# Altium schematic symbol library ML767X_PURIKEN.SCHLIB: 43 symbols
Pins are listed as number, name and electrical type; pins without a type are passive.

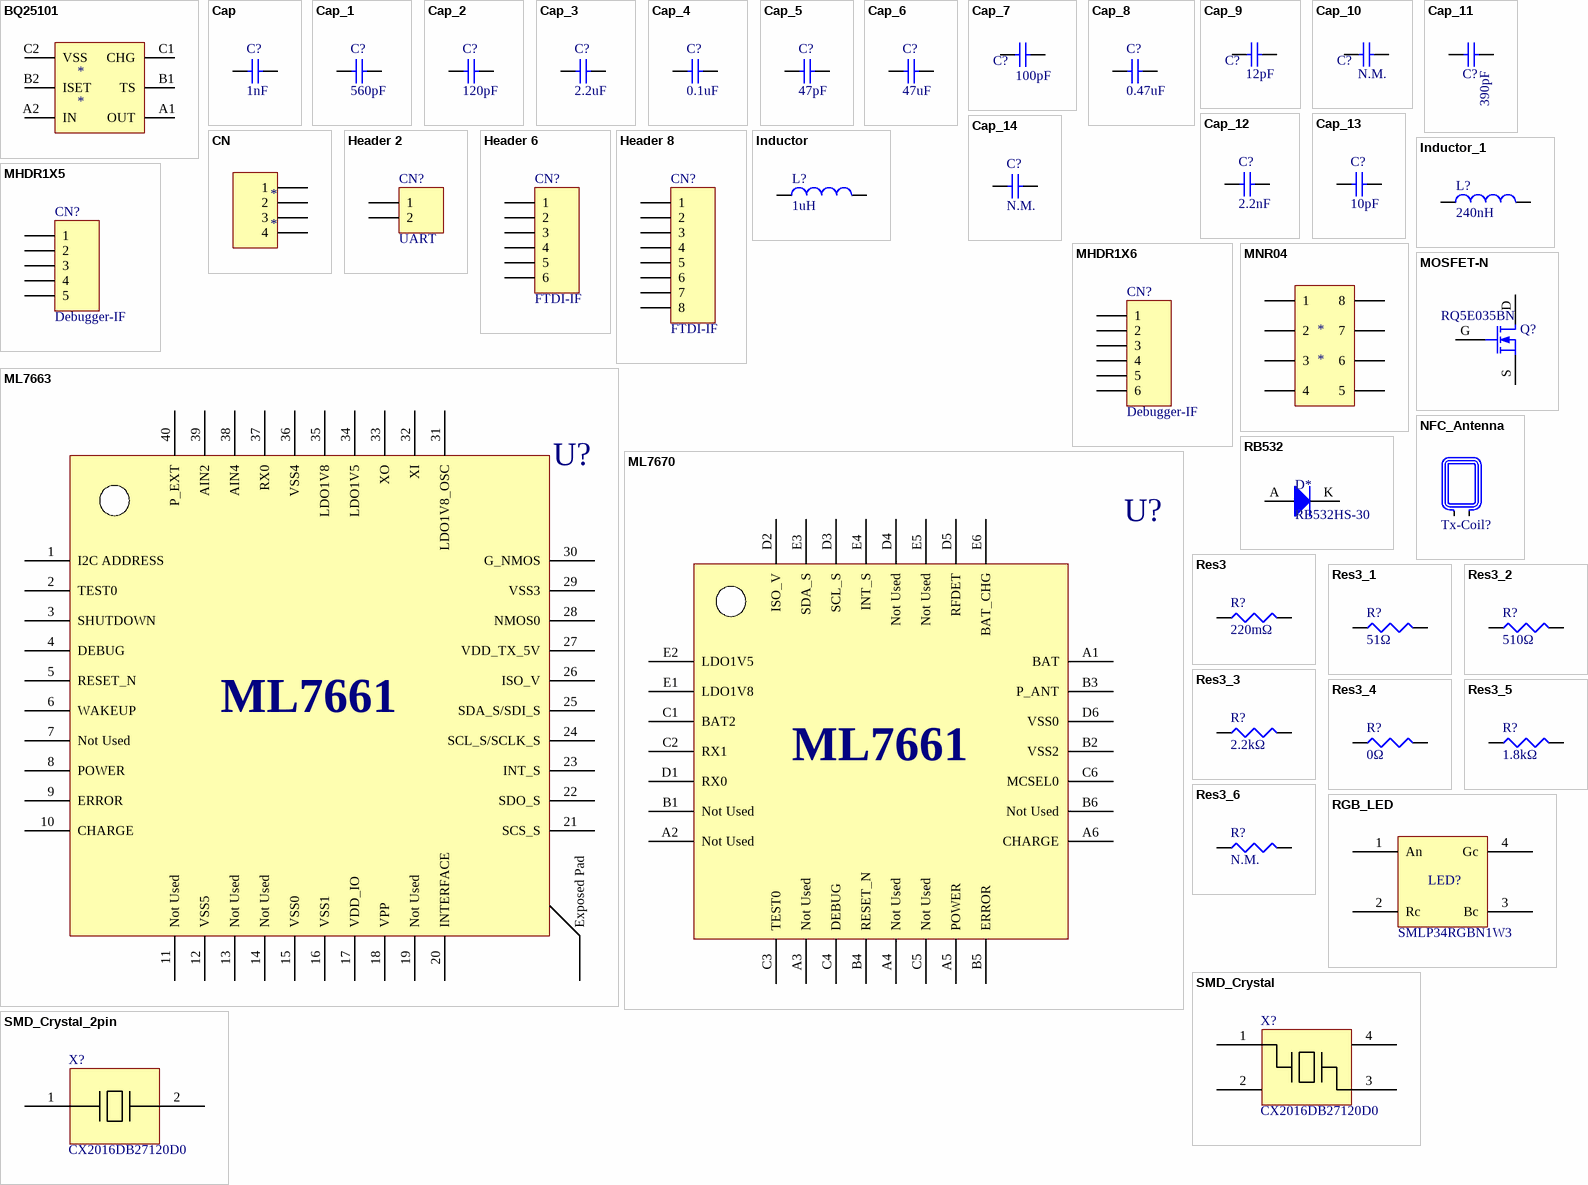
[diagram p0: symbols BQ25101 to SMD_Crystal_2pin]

## BQ25101
designator *
footprint DSBGA (YFP)
pins: A1 OUT, A2 IN, B1 TS, B2 ISET, C1 CHG, C2 VSS

## Cap
designator C?  value 1nF  (hidden comment: Cap)
Capacitor; Part Number: GRM0335C1E102FA01#; Note: 25Vdc,1%; Maker: Murata
footprint CAPC0603X03L_C
footprint 0603-1_00
pins: 1, 2

## Cap_1
designator C?, comment value 560pF  (hidden comment: Cap)
Capacitor; Part Number: GRM033R71C561KA01#; Note: 16Vdc,10%; Maker: Murata
footprint CAPC0603X03L_C
footprint 0603-1_00
pins: 1, 2

## Cap_2
designator C?, comment value 120pF  (hidden comment: Cap)
Capacitor; Part Number: GCM1555C1H121FA16#; Note: 50Vdc,1%,matching; Maker: Murata
footprint CAPC1005X04L
footprint CC1005_02
pins: 1, 2

## Cap_3
designator C?, comment value 2.2uF  (hidden comment: Cap)
Capacitor; Part Number: GRM035R61C225ME01#; Note: 16Vdc,20%; Maker: Murata
footprint CAPC0603X03L_C
footprint 0603-1_00
pins: 1, 2

## Cap_4
designator C?, comment value 0.1uF  (hidden comment: Cap)
Capacitor; Part Number: GRM033R61C104KE18#; Note: 16Vdc,10%; Maker: Murata
footprint CAPC0603X03L_C
footprint 0603-1_00
pins: 1, 2

## Cap_5
designator C?, comment value 47pF  (hidden comment: Cap)
Capacitor; Part Number: GRM0335C1H470FA01#; Note: 50Vdc,1%; Maker: Murata
footprint CAPC0603X03L_C
footprint 0603-1_00
pins: 1, 2

## Cap_6
designator C?, comment value 47uF  (hidden comment: Cap)
Capacitor; Part Number: GRM21BR61A476ME15#; Note: 10Vdc,20%; Maker: Murata
footprint Model Name (Footprint not found)
footprint CAPC2012X11L
footprint GCM21_2125_00
pins: 1, 2

## Cap_7
designator C?, comment value 100pF  (hidden comment: Cap)
Capacitor; Part Number: C0402C101F2GACAUTO; Note: 200Vdc,1%,matching; Maker: KEMET
footprint CAPC1005X04L
footprint CC1005_02
pins: 1, 2

## Cap_8
designator C?, comment value 0.47uF  (hidden comment: Cap)
Capacitor; Part Number: GRM033R60J474KE90#; Note: 6.3Vdc,10%; Maker: Murata
footprint CAPC0603X03L_C
footprint 0603-1_00
pins: 1, 2

## Cap_9
designator C?, comment value 12pF  (hidden comment: Cap)
Capacitor; Part Number: GQM1555C2D120FB01D; Note: 200Vdc,1%,matching; Maker: Murata
footprint CAPC1005X04L
footprint CC1005_02
pins: 1, 2

## Cap_10
designator C?, comment value N.M.  (hidden comment: Cap)
Capacitor
footprint CAPC1005X04L
footprint CC1005_02
pins: 1, 2

## Cap_11
designator C?, comment value 390pF  (hidden comment: Cap)
Capacitor; Part Number: GRM1555C1H391FA01#; Note: 50Vdc,1%,matching; Maker: Murata
footprint CAPC1005X04L
footprint CC1005_02
pins: 1, 2

## Cap_12
designator C?, comment value 2.2nF  (hidden comment: Cap)
Capacitor; Part Number: GCM1885C1H222GA16#; Note: 50Vdc,2%,matching; Maker: Murata
footprint CAPC1608X06L
footprint CC1608_00
pins: 1, 2

## Cap_13
designator C?, comment value 10pF  (hidden comment: Cap)
Capacitor; Part Number: GRM0335C1H100FA01#; Note: 50Vdc,1%; Maker: Murata
footprint CAPC0603X03L_C
footprint 0603-1_00
pins: 1, 2

## Cap_14
designator C?, comment N.M.
Capacitor
footprint CAPC1005X04L
footprint CC1005_02
pins: 1, 2

## CN
designator *
pins: 1, 2, 3, 4

## Header 2
designator CN?  Note: UART  (hidden comment: Header 2)
Header, 2-Pin; Part Number: PH-1x2SG; Value: 2-Pin Header
footprint HDR1X2 (Connector; Header; 2 Position)
footprint JP2-2.54_01
pins: 1, 2

## Header 6
designator CN?  Note: FTDI-IF  (hidden comment: Header 6)
Header, 6-Pin; Part Number: PH-1x8SG; Value: 6-Pin Header
signal-integrity model Connector
footprint JP6-2.54_01
pins: 1, 2, 3, 4, 5, 6

## Header 8
designator CN?  Note: FTDI-IF  (hidden comment: Header 8)
Header, 8-Pin; Part Number: PH-1x8SG; Value: 8-Pin Header
signal-integrity model Connector
footprint HDR1X8 (Connector; Header; 8 Position)
footprint JP8-2.54_01
pins: 1, 2, 3, 4, 5, 6, 7, 8

## Inductor
designator L?, comment 1uH
Inductor; Part Number: LQM2MPN1R0MGH#; Maker: Murata
footprint LQM2MPN1R0NG0L (1uH)
footprint LQM2MP_00
pins: 1, 2

## Inductor_1
designator L?, comment 240nH
Inductor; Part Number: LQM2MPNR24MEHL; Maker: Murata
footprint LQM2MPNR24MEHL (240nH)
footprint LQM2MP_00
pins: 1, 2

## MHDR1X5
designator CN?  Note: Debugger-IF  (hidden comment: MHDR1X5)
Header, 6-Pin; Part Number: XB-1-5-6P; Value: 5-Pin Header
signal-integrity model Connector
footprint MHDR1X6 (Connector; Header; 6 Position)
footprint CN5_XB-1-5 (XB-1-5-5P プリント板ニ段重ね用コンスルー)
pins: 1, 2, 3, 4, 5

## MHDR1X6
designator CN?  Note: Debugger-IF  (hidden comment: MHDR1X6)
Header, 6-Pin; Part Number: XB-1-5-6P; Value: 6-Pin Header
signal-integrity model Connector
footprint MHDR1X6 (Connector; Header; 6 Position)
footprint CN6_XB-1-5 (XB-1-5-6P プリント板ニ段重ね用コンスルー)
pins: 1, 2, 3, 4, 5, 6

## ML7663
designator U?, comment -  (value not drawn)
NFC TX, WQFN40; Part Number: ML7661; Maker: Rohm; Note: WQFN-40pin
footprint QFN40P500X500X50_HS-41N
footprint P-WQFN40-0606-0.50_00
footprint QFN50P600X600X80_41N_ROHM (QFN, 40-Leads, Body 6.00x6.00mm, Pitch 0.50mm, Thermal Pad 4.20x4.20mm)
pins: 1 I2C ADDRESS, 2 TEST0, 3 SHUTDOWN, 4 DEBUG, 5 RESET_N, 6 WAKEUP, 7 Not Used, 8 POWER, 9 ERROR, 10 CHARGE, 11 Not Used, 12 VSS5, 13 Not Used, 14 Not Used, 15 VSS0, 16 VSS1, 17 VDD_IO, 18 VPP, 19 Not Used, 20 INTERFACE, 21 SCS_S, 22 SDO_S, 23 INT_S, 24 SCL_S/SCLK_S, 25 SDA_S/SDI_S, 26 ISO_V, 27 VDD_TX_5V, 28 NMOS0, 29 VSS3, 30 G_NMOS, 31 LDO1V8_OSC, 32 XI, 33 XO, 34 LDO1V5, 35 LDO1V8, 36 VSS4, 37 RX0, 38 AIN4, 39 AIN2, 40 P_EXT, 41 Exposed Pad

## ML7670
designator U?, comment -  (value not drawn)
NFC TX, WQFN40; Part Number: ML7661; Maker: Rohm; Note: WQFN-40pin
footprint QFN40P500X500X50_HS-41N
footprint P-WQFN40-0606-0.50_00
footprint ML7670_WL-CSP30_00
pins: A1 BAT, A2 Not Used, A3 Not Used, A4 Not Used, A5 POWER, A6 CHARGE, B1 Not Used, B2 VSS2, B3 P_ANT, B4 RESET_N, B5 ERROR, B6 Not Used, C1 BAT2, C2 RX1, C3 TEST0, C4 DEBUG, C5 Not Used, C6 MCSEL0, D1 RX0, D2 ISO_V, D3 SCL_S, D4 Not Used, D5 RFDET, D6 VSS0, E1 LDO1V8, E2 LDO1V5, E3 SDA_S, E4 INT_S, E5 Not Used, E6 BAT_CHG

## MNR04
designator *
pins: 1 2, 1 3, 1 7, 1 6, 1 4, 1 5, 1 8, 1

## MOSFET-N
designator Q?, comment RQ5E035BN
N-Channel MOSFET; Maker: Rohm
footprint RQ5E035BNTCL
footprint TSMT3_GDS_ROHM_00
pins: D, G, S

## NFC_Antenna
designator Tx-Coil?, comment -  (value not drawn)
NFC Antenna; Part Number: 「S24-T6」
footprint Tx-Coil1
pins: 1, 2

## RB532
designator D*, comment RB532HS-30
pins: A, K

## Res3
designator R?, comment 220mΩ
Resistor; Part Number: LTR10LEZPFLR220; Maker: Rohm; Note: 1W,±1%
footprint RESC1220X70N
footprint LTR10_00
pins: 1, 2

## Res3_1
designator R?, comment 51Ω
Resistor; Part Number: MCR01MZPJ510; Maker: Rohm; Note: 0.1W,±5%
footprint RESC1005X04L
footprint RR1005_02
pins: 1, 2

## Res3_2
designator R?, comment 510Ω
Resistor; Part Number: MCR01MZPJ511; Maker: Rohm; Note: 0.1W,±5%
footprint RESC1005X04L
footprint RR1005_02
pins: 1, 2

## Res3_3
designator R?, comment 2.2kΩ
Resistor; Part Number: MCR01MZPJ222; Maker: Rohm; Note: 0.05W,±5%, Pull-up
footprint RESC1005X04L
footprint RR1005_02
pins: 1, 2

## Res3_4
designator R?, comment 0Ω
Resistor; Part Number: PMR01HZPJ000; Maker: Rohm
footprint RESC1005X04L
footprint RR1005_02
pins: 1, 2

## Res3_5
designator R?, comment 1.8kΩ
Resistor; Part Number: MCR01MZPJ182; Maker: Rohm
footprint RESC1005X04L
footprint RR1005_02
pins: 1, 2

## Res3_6
designator R?, comment N.M.
Resistor
footprint RESC1005X04L
footprint RR1005_02
pins: 1, 2

## RGB_LED
designator LED?, comment SMLP34RGBN1W3
RGB LED; Note: 3-color LED; Maker: Rohm
footprint SMLP34RGB1W3
footprint SMLP34RGB_00
pins: 1 An, 2 Rc, 3 Bc, 4 Gc (power)

## SMD_Crystal
designator X?, comment CX2016DB27120D0
SMD Crystal; Maker: Kyocera
footprint BT-XTAL_2016
footprint CX2016DB_00
pins: 1, 2 4, 3, 4

## SMD_Crystal_2pin
designator X?, comment CX2016DB27120D0
SMD Crystal 2pin; Maker: Kyocera
footprint BT-XTAL_2016
footprint CX2016DB_00
pins: 1, 2

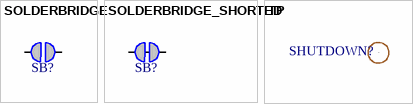
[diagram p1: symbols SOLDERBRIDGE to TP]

## SOLDERBRIDGE
designator SB?, comment Solderbridge  (value not drawn)
footprint Solderbridge
pins: 1 0, 2 1

## SOLDERBRIDGE_SHORTED
designator SB?, comment Solderbridge Shorted  (value not drawn)
Shorted Solderbridge
footprint Solderbridge_Shorted
footprint Solderbridge_Shorted_Power
pins: 1 0, 2 1

## TP
designator SHUTDOWN?
TP; Value: Small Pad
footprint TP_PAD1.0_03
pins: 1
